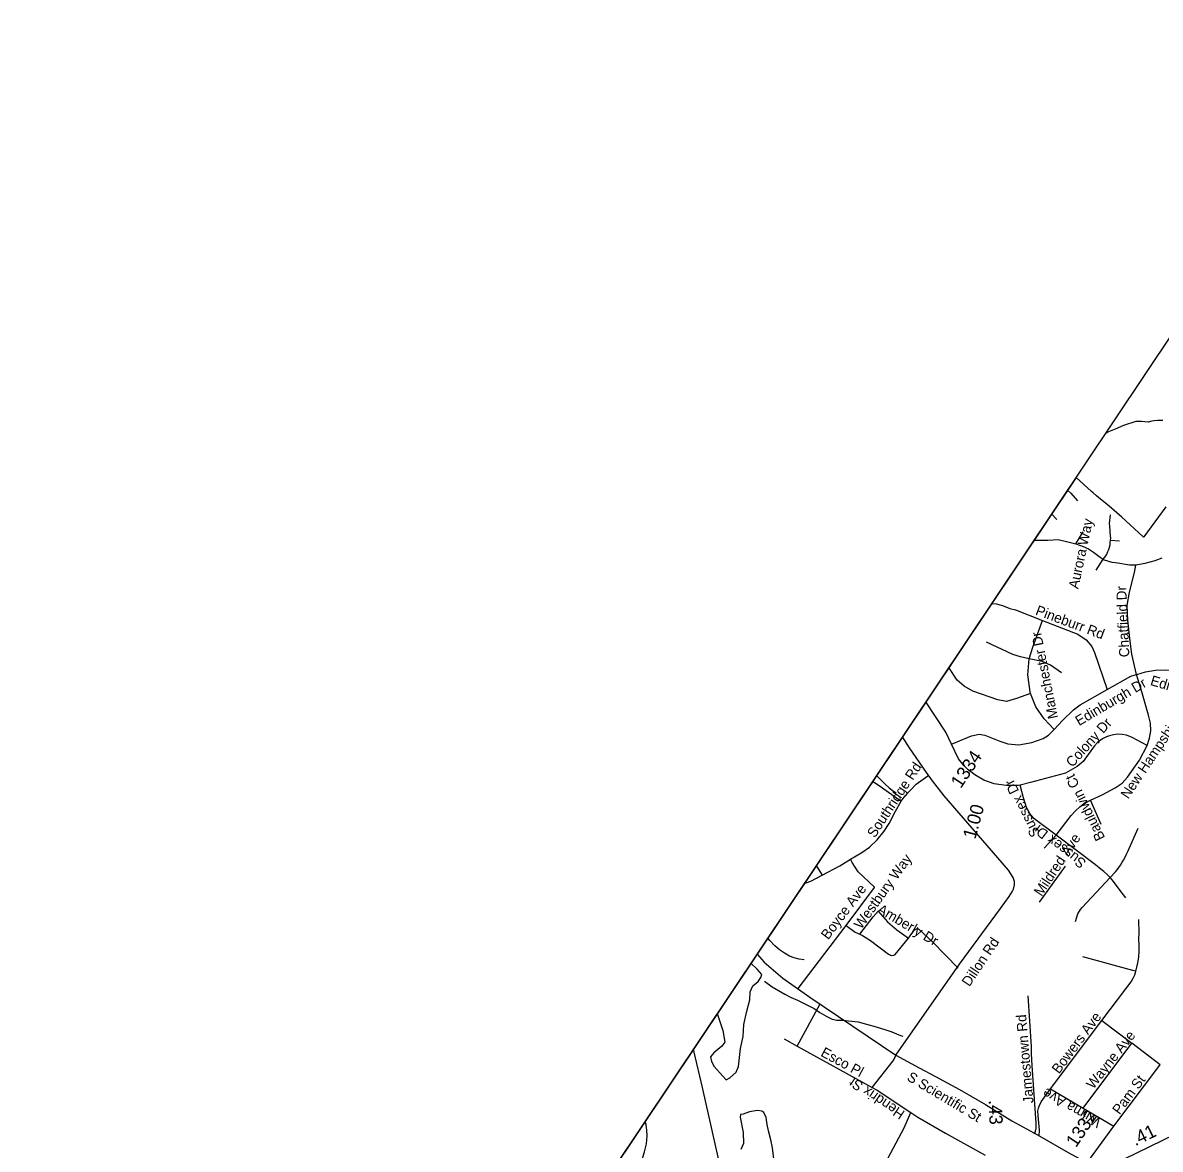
# Model space of a CAD drawing. Extents: x 1715610 to 1720914, y 798298 to 802505.
# Drawn here: x 1715610 to 1715843.1, y 799705.3 to 799936.1 of the extents above; entities that cross this region are included whole.
import ezdxf

# ---------------------------------------------------------------- set-up
doc = ezdxf.new("R2010")
doc.units = 0
doc.layers.add('Default', color=7, linetype='Continuous')
doc.layers.add('Prop DSN Text', color=7, linetype='Continuous')

msp = doc.modelspace()

# ---------------------------------------------------------------- linework, layer by layer
at = {"layer": 'Default'}
for p, q in [((1715825.88, 799842.99), (1715610.03, 799520.5)), ((1715825.88, 799842.99), (1715610.03, 799520.5)), ((1715825.81, 799829.36), (1715827.33, 799831.85)), ((1715834.81, 799829.91), (1715832.97, 799830.03)), ((1715829.99, 799823.98), (1715831.47, 799826.21)), ((1715831, 799771.86), (1715828.85, 799776.88)), ((1715819.36, 799767.01), (1715821.79, 799769.66)), ((1715818.39, 799755.96), (1715823.74, 799763.36)), ((1715768.93, 799738.29), (1715778.75, 799751.16)), ((1715768.73, 799726.44), (1715773.48, 799735.13)), ((1715820.67, 799717.73), (1715831.19, 799731.72)), ((1715831.19, 799731.72), (1715837.31, 799727.06)), ((1715766.07, 799727.95), (1715768.73, 799726.44)), ((1715768.73, 799726.44), (1715784.13, 799718)), ((1715827.36, 799713.77), (1715837.31, 799727.06)), ((1715820.67, 799717.73), (1715827.36, 799713.77)), ((1715827.36, 799713.77), (1715833.65, 799710.05)), ((1715828.11, 799702.49), (1715833.65, 799710.05)), ((1715817.39, 799708.5), (1715817.4, 799708.52))]:
    msp.add_line(p, q, dxfattribs=at)
for points in [[(1715840.64, 799854.3), (1715839.32, 799854.46), (1715838.14, 799854.43), (1715835.58, 799853.6), (1715833.89, 799852.9), (1715832.53, 799852.3), (1715831.91, 799852)], [(1715843.65, 799854.62), (1715842.55, 799854.63), (1715841.87, 799854.56), (1715841.41, 799854.51), (1715840.64, 799854.3)], [(1715844.3, 799836.97), (1715839.77, 799830.84), (1715839.71, 799830.77), (1715839.57, 799830.9), (1715835.3, 799834.87), (1715832.65, 799837.09), (1715830.51, 799838.88), (1715830.07, 799839.24), (1715829.37, 799839.8), (1715829.05, 799840.1), (1715825.88, 799842.99)], [(1715844.3, 799836.97), (1715839.77, 799830.84), (1715839.71, 799830.77), (1715839.57, 799830.9), (1715835.3, 799834.87), (1715832.65, 799837.09), (1715830.51, 799838.88), (1715830.07, 799839.24), (1715829.37, 799839.8), (1715829.05, 799840.1), (1715825.88, 799842.99)], [(1715824.11, 799840.34), (1715824.2, 799840.3), (1715824.8, 799839.73), (1715826.17, 799838.19)], [(1715821.93, 799834.38), (1715820.88, 799835.52)], [(1715832.97, 799830.03), (1715832.98, 799830.58), (1715832.97, 799830.93), (1715832.78, 799832.99), (1715832.75, 799833.53), (1715832.8, 799834.18), (1715832.88, 799834.73), (1715832.97, 799835.29)], [(1715817.28, 799830.14), (1715817.39, 799830.13)], [(1715817.39, 799830.13), (1715817.4, 799830.32)], [(1715817.39, 799830.13), (1715820.1, 799830.14), (1715822.24, 799830.26), (1715824.18, 799829.82), (1715825.81, 799829.36)], [(1715825.81, 799829.36), (1715827.33, 799828.84), (1715828.46, 799828.34), (1715829.46, 799827.67), (1715830.28, 799827.07), (1715830.8, 799826.65), (1715831.47, 799826.21)], [(1715831.47, 799826.21), (1715831.87, 799826.72), (1715832.11, 799827.13), (1715832.23, 799827.39), (1715832.41, 799827.79), (1715832.58, 799828.2), (1715832.72, 799828.67), (1715832.85, 799829.19), (1715832.91, 799829.62), (1715832.97, 799830.03)], [(1715831.47, 799826.21), (1715831.64, 799826.11), (1715833.2, 799825.6), (1715833.89, 799825.52), (1715834.44, 799825.45), (1715836.84, 799825.05), (1715838.11, 799825.07)], [(1715838.11, 799825.07), (1715840.04, 799825.39), (1715842.12, 799825.96), (1715843.5, 799826.51)], [(1715838.24, 799802.61), (1715837.33, 799806.76), (1715836.88, 799810), (1715836.52, 799813.74), (1715836.36, 799816.72), (1715836.85, 799819.48), (1715837.91, 799823.79), (1715838.11, 799825.07)], [(1715808.6, 799817.17), (1715809.49, 799817.08), (1715810.79, 799816.76), (1715812.33, 799816.13), (1715813.46, 799815.82), (1715818.98, 799813.64)], [(1715816.27, 799805.83), (1715817, 799808.21), (1715818.98, 799813.64)], [(1715818.98, 799813.64), (1715826.26, 799810.86), (1715827.96, 799809.73), (1715829.09, 799808.32), (1715829.67, 799807.11), (1715832.28, 799799.5)], [(1715816.27, 799805.83), (1715814.53, 799806.22), (1715812.9, 799806.7), (1715807.51, 799809.21)], [(1715816.57, 799798.74), (1715816.46, 799799.02), (1715816.02, 799802.56), (1715816.27, 799805.83)], [(1715822.89, 799802.95), (1715820.67, 799804.52), (1715818.96, 799805.24), (1715816.27, 799805.83)], [(1715816.57, 799798.74), (1715813.7, 799797.69), (1715811.66, 799797.08), (1715809.84, 799797.38), (1715804.72, 799799.16), (1715802.95, 799800.19), (1715801.49, 799801.47), (1715799.8, 799804.03)], [(1715832.28, 799799.5), (1715837.12, 799802.25), (1715838.24, 799802.61)], [(1715838.24, 799802.61), (1715838.31, 799802.63), (1715840.12, 799803.17), (1715842.18, 799803.5), (1715844.27, 799803.57), (1715846.26, 799803.41)], [(1715840.43, 799788.04), (1715840.97, 799789.57), (1715841.18, 799791.05), (1715841.13, 799792.66), (1715840.74, 799794.27), (1715839.37, 799799.03), (1715838.24, 799802.61)], [(1715821.38, 799791.36), (1715819.32, 799793.5), (1715817.66, 799795.99), (1715816.57, 799798.74)], [(1715821.38, 799791.36), (1715823.08, 799793.16), (1715825.33, 799795.38), (1715826.7, 799796.41), (1715832.28, 799799.5)], [(1715800.36, 799788.32), (1715799.17, 799790.78), (1715795.11, 799797.03)], [(1715800.36, 799788.32), (1715804.47, 799790.03), (1715806.02, 799790.37), (1715807.17, 799790.17), (1715810.26, 799788.91), (1715811.9, 799788.43), (1715814.19, 799788.18), (1715816.82, 799788.65), (1715819.16, 799789.52), (1715820.26, 799790.19), (1715821.38, 799791.36)], [(1715788.95, 799724.59), (1715802.02, 799743.22), (1715810.38, 799754.64), (1715812.2, 799757.12), (1715812.89, 799758.21), (1715813.06, 799758.6), (1715813.28, 799759.49), (1715813.28, 799759.5), (1715813.3, 799760.17), (1715812.98, 799760.98), (1715812.02, 799762.49), (1715807.67, 799767.55), (1715798.86, 799777.74), (1715796.45, 799780.84), (1715795.21, 799782.51), (1715791.75, 799787.59), (1715790.29, 799789.83)], [(1715840.43, 799788.04), (1715837.42, 799789.69), (1715836.2, 799790.15), (1715835.33, 799790.31), (1715834.45, 799790.36), (1715833.59, 799790.27), (1715832.73, 799790.07), (1715832.11, 799789.85), (1715831.42, 799789.51), (1715830.87, 799789.14), (1715830.28, 799788.64), (1715829.67, 799787.98), (1715828.39, 799786.18), (1715827.33, 799784.8), (1715826.13, 799783.75), (1715823.71, 799782.42), (1715816.58, 799780.44), (1715814.43, 799779.95)], [(1715814.43, 799779.95), (1715814.03, 799779.86), (1715811.54, 799779.84), (1715809.09, 799780.22), (1715806.99, 799780.94), (1715805.17, 799782.04), (1715803.81, 799783.04), (1715802.95, 799783.89), (1715801.8, 799785.32), (1715800.36, 799788.32)], [(1715828.85, 799776.88), (1715831.21, 799777.98), (1715833.9, 799779.35), (1715835.34, 799780.35), (1715836.46, 799781.55), (1715838.9, 799785.05), (1715840.43, 799788.04)], [(1715785.01, 799781.92), (1715785.45, 799781.45), (1715786.79, 799780.11), (1715787.58, 799779.41), (1715788.5, 799778.68), (1715789.01, 799778.33)], [(1715790.08, 799776.66), (1715790.84, 799777.72), (1715793.1, 799780.13), (1715795.52, 799781.84)], [(1715783.75, 799780.05), (1715784.38, 799780.58)], [(1715784.23, 799780.77), (1715784.38, 799780.58)], [(1715784.38, 799780.58), (1715785.51, 799779.89), (1715790.08, 799776.66)], [(1715821.79, 799769.66), (1715817.21, 799773.09), (1715816.39, 799774.13), (1715815.76, 799775.38), (1715815.15, 799777.31), (1715814.43, 799779.95)], [(1715821.79, 799769.66), (1715824.87, 799773.69), (1715825.76, 799774.67), (1715826.65, 799775.5), (1715827.8, 799776.34), (1715828.85, 799776.88)], [(1715779.66, 799764.79), (1715782.01, 799766.15), (1715783.59, 799767.2), (1715785.12, 799768.71), (1715786.55, 799770.49), (1715787.56, 799772.06), (1715788.88, 799774.59), (1715790.08, 799776.66)], [(1715832.87, 799760.98), (1715833.95, 799762.17), (1715834.31, 799762.61), (1715834.65, 799763.08), (1715834.98, 799763.55), (1715835.29, 799764.03), (1715835.58, 799764.53), (1715836, 799765.28), (1715836.24, 799765.8), (1715836.47, 799766.33), (1715838.63, 799771.09)], [(1715832.87, 799760.98), (1715832.25, 799761.62), (1715831.57, 799762.24), (1715831.04, 799762.67), (1715829.84, 799763.59), (1715821.79, 799769.66)], [(1715772.66, 799763.48), (1715772.72, 799763.33), (1715773.83, 799761.49)], [(1715773.83, 799761.49), (1715777.48, 799763.43), (1715779.66, 799764.79)], [(1715778.75, 799751.16), (1715784.6, 799758.97), (1715784.57, 799759), (1715781.26, 799762.17), (1715780.02, 799764.08), (1715779.66, 799764.79)], [(1715770.19, 799759.79), (1715770.6, 799759.89), (1715771.55, 799760.24), (1715773.83, 799761.49)], [(1715825.78, 799751.99), (1715826.24, 799753.53), (1715826.79, 799754.46), (1715827.11, 799754.89), (1715832.87, 799760.98)], [(1715836.11, 799756.87), (1715835.15, 799758.08), (1715833.33, 799760.43), (1715832.87, 799760.98)], [(1715781.57, 799749.41), (1715784.29, 799752.93), (1715785.3, 799754.14), (1715787.22, 799751.93), (1715789.19, 799750.28), (1715791.52, 799748.61)], [(1715778.75, 799751.16), (1715780.65, 799749.84), (1715781.57, 799749.41)], [(1715838.12, 799741.8), (1715838.33, 799742.63), (1715838.55, 799743.53), (1715838.72, 799744.67), (1715838.8, 799745.93), (1715838.81, 799747.06), (1715838.77, 799748.48), (1715838.82, 799749.56), (1715838.75, 799752.39)], [(1715781.57, 799749.41), (1715782.13, 799749.14), (1715783.79, 799748.08), (1715787.46, 799745.28), (1715787.84, 799745.11), (1715788.12, 799745.06), (1715788.54, 799745.1), (1715788.8, 799745.2), (1715791.52, 799748.61)], [(1715791.52, 799748.61), (1715792.81, 799750.27), (1715793.19, 799750.47), (1715793.57, 799750.49), (1715796.47, 799747.84), (1715801.75, 799742.46)], [(1715770.14, 799744.16), (1715769.12, 799744.28), (1715768.1, 799744.56), (1715767.19, 799744.86), (1715766.14, 799745.48), (1715765.12, 799746.22), (1715764.19, 799747.02), (1715763.14, 799748.1), (1715762.69, 799748.58)], [(1715760.53, 799745.36), (1715760.57, 799745.3), (1715761.99, 799743.69), (1715765.79, 799740.35), (1715771.3, 799736.5), (1715788.95, 799724.59)], [(1715838.12, 799741.8), (1715837.55, 799741.95), (1715827.26, 799744.72)], [(1715752.36, 799733.14), (1715753.52, 799729.68), (1715753.94, 799727.29), (1715753.28, 799726.43), (1715751.66, 799725.09), (1715750.95, 799724.27), (1715751.19, 799723.29), (1715751.73, 799722.29), (1715753.42, 799720.34), (1715754.17, 799719.52), (1715754.95, 799719.96), (1715756.22, 799721.14), (1715756.73, 799722.26), (1715757.11, 799725.97), (1715757.64, 799728.46), (1715757.83, 799730.92), (1715758.42, 799733.61), (1715759.02, 799735.96), (1715759.13, 799737.59), (1715759.62, 799738.8), (1715760.71, 799739.7), (1715761.32, 799740.5), (1715761.49, 799741.11), (1715760.54, 799742.24), (1715759.24, 799743.43)], [(1715831.19, 799731.72), (1715836.06, 799738.21), (1715837.16, 799739.64), (1715837.61, 799740.4), (1715837.91, 799741.08), (1715838.12, 799741.8)], [(1715762.04, 799739.79), (1715763.61, 799738.61), (1715766.21, 799737.1), (1715767.5, 799736.43), (1715768.79, 799735.86), (1715771.28, 799734.64), (1715772.22, 799734.16), (1715773.36, 799733.37), (1715774.78, 799732.51), (1715775.88, 799731.97), (1715776.89, 799731.75), (1715777.96, 799731.76), (1715781.21, 799731.44), (1715782.93, 799730.95), (1715784.92, 799730.38), (1715786.9, 799729.82), (1715788.11, 799729.36), (1715789.1, 799728.95), (1715789.88, 799728.62), (1715790.4, 799728.53)], [(1715831.51, 799700.23), (1715832.34, 799701), (1715833.68, 799702.12), (1715835.83, 799703.33), (1715846.23, 799708.39), (1715860.3, 799713.75), (1715865.13, 799715.4), (1715867.52, 799716.4), (1715869.21, 799717.62), (1715871.02, 799719.25), (1715879.25, 799726.89), (1715883.32, 799730.86), (1715890.44, 799737.32), (1715894.28, 799741.38)], [(1715817.4, 799708.52), (1715817.53, 799708.83), (1715817.61, 799709.04), (1715817.67, 799709.37), (1715817.68, 799709.51), (1715817.7, 799710.64), (1715816.88, 799722.5), (1715816.75, 799724.86), (1715816.77, 799725.75), (1715816.78, 799726.39), (1715816.06, 799736.76)], [(1715753.74, 799698.23), (1715751.33, 799709.2), (1715749.32, 799718), (1715747.63, 799725.24), (1715747.5, 799725.89)], [(1715833.65, 799710.05), (1715843.06, 799722.59), (1715843.09, 799722.64), (1715837.31, 799727.06)], [(1715784.13, 799718), (1715788.39, 799723.42), (1715788.97, 799724.44)], [(1715788.95, 799724.59), (1715793.74, 799721.98), (1715797.1, 799720.24), (1715801.98, 799717.56), (1715807.32, 799714.53), (1715812.73, 799711.18), (1715818, 799708.29), (1715824.25, 799704.66), (1715828.17, 799702.54), (1715831.51, 799700.23)], [(1715784.13, 799718), (1715785.15, 799717.43), (1715792.02, 799712.87)], [(1715818.34, 799707.99), (1715818.39, 799709.25), (1715818.1, 799712.24), (1715818.08, 799713.22), (1715818.21, 799713.76), (1715818.33, 799714.16), (1715818.76, 799715.03), (1715820.67, 799717.73)], [(1715758.94, 799712.98), (1715757.67, 799712.55), (1715757.1, 799712.44), (1715757.08, 799711.88), (1715757.66, 799708.73), (1715757.72, 799706.49), (1715757.2, 799705.28)], [(1715763.94, 799703.39), (1715763.71, 799705.6), (1715763.34, 799707.27), (1715762.89, 799709.13), (1715762.6, 799710.39), (1715762.36, 799711.83), (1715761.9, 799712.84), (1715761.46, 799713.14), (1715760.58, 799713.3), (1715758.94, 799712.98)], [(1715787.37, 799703.55), (1715790.65, 799709.73), (1715792.02, 799712.87)], [(1715792.02, 799712.87), (1715793.45, 799711.92), (1715799.16, 799708.59), (1715807.26, 799704.1)], [(1715730.7, 799694.14), (1715734.91, 799699.49), (1715735.54, 799700.43), (1715736.24, 799701.66), (1715736.94, 799703.2), (1715737.47, 799704.81), (1715737.83, 799706.47), (1715737.98, 799708.09), (1715737.93, 799709.22), (1715737.76, 799710.32), (1715737.57, 799711.06)]]:
    msp.add_lwpolyline(points, dxfattribs=at)
at = {"layer": 'Prop DSN Text'}
msp.add_lwpolyline([(1715972.32, 799278.02), (1716250.51, 799693.66), (1715888.23, 799936.14), (1715610.03, 799520.5)], close=True, dxfattribs=at)

# ---------------------------------------------------------------- texts
at = {"layer": 'Default'}
for s, height, rotation, p in [('Aurora Way', 2.066, 78.0179, (1715826.34, 799820.03)), ('Chatfield Dr', 2.0663, 92.5942, (1715836.82, 799806.19)), ('Pineburr Rd', 2.0663, 339.5858, (1715817.42, 799814.92)), ('Manchester Dr', 2.0663, 101.2216, (1715822.2, 799793.73)), ('Edinburgh Dr', 2.0663, 343.2985, (1715840.96, 799800.49)), ('Edinburgh Dr', 2.0663, 30.4822, (1715826.5, 799792.01)), ('New Hampshire Dr', 2.0663, 56.2051, (1715836.58, 799776.96)), ('Colony Dr', 2.066, 47.7823, (1715825.13, 799783.46)), ('1334', 2.719, 56.2051, (1715802.27, 799779.11)), ('Southridge Rd', 2.0663, 56.6356, (1715784.64, 799768.99)), ('Bauldwin Ct', 2.0663, 115.8958, (1715831.88, 799769.14)), ('Sussex Dr', 2.066, 116.0497, (1715818.57, 799769.9)), ('1.00', 2.719, 74.6272, (1715805.23, 799768.73)), ('Sussex Dr', 2.066, 142.2891, (1715828.13, 799764.32)), ('Mildred Ave', 2.0663, 56.2051, (1715818.82, 799757.01)), ('Westbury Way', 2.0663, 54.3495, (1715781.88, 799750.28)), ('Boyce Ave', 2.066, 52.8683, (1715775.08, 799748.13)), ('Amberly Dr', 2.066, 329.5425, (1715784.97, 799753.92)), ('Dillon Rd', 2.066, 56.2051, (1715804.03, 799738.51)), ('Jamestown Rd', 2.0663, 94.843, (1715817.18, 799714.81)), ('Bowers Ave', 2.066, 53.3036, (1715822.39, 799720.64)), ('Wayne Ave', 2.066, 51.7443, (1715829.43, 799717.51)), ('Esco Pl', 2.066, 331.4448, (1715773.39, 799724.54)), ('S Scientific St', 2.0663, 329.1587, (1715791.06, 799719.57)), ('Hendrix St', 2.066, 145.9324, (1715790.97, 799713.02)), ('Pam St', 2.066, 53.3829, (1715834.8, 799712.28)), ('Wilma Ave', 2.066, 150.0597, (1715831.23, 799711.4)), ('.43', 2.719, 272.047, (1715807.99, 799715.37)), ('1332', 2.719, 56.2051, (1715825.87, 799705.52)), ('.41', 2.719, 25.9202, (1715838.03, 799705.92))]:
    msp.add_text(s, height=height, rotation=rotation, dxfattribs=at).set_placement(p)

doc.saveas('drawing.dxf')
